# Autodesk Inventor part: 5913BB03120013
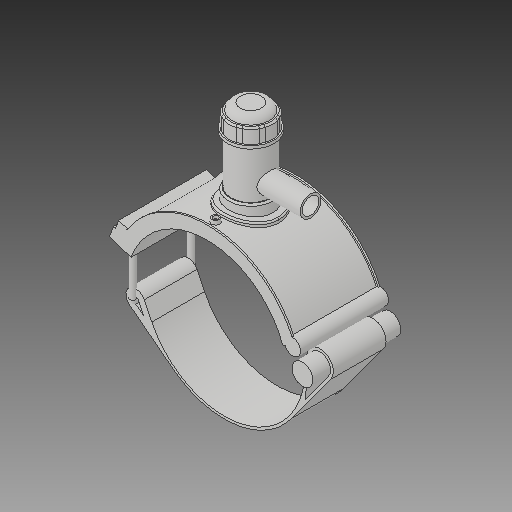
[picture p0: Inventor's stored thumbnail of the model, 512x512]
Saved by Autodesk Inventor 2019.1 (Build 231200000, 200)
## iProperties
Created: 2017-07
Part Number: 5913BB03120013
Material: Generic
Description: PLASSON HIGH VOLUME TAPPING TEE 12''IPS x 1 1/4''IPS
Document SubType Name: Modeling
Designer: KIM
Mass: 1712.7 g
Surface Area: 2671.49 cm^2
Volume: 1712.7 cm^3
Density: 1 g/cm^3
Appearance: Default
Author: KIM
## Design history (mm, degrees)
derived "5913B.ipt"
feature "Solid1::5913B.ipt"
feature "Solid2::5913B.ipt"
feature "Solid4::5913B.ipt"
feature "Solid5::5913B.ipt"
tag "TaggingFeature1"
body "Solid1"
body "Solid2"
other parameters: "d0" = 323.4, "d2" = 487.045, "d3" = 80.85, "d4" = 176.022, "d5" = 0, "d6" = 0.1, "d8" = 0, "d40" = 191.71152, "d41" = 113.19, "d43" = 0, "d45" = 0, "d47" = 289.9512, "d78" = 191.7, "d79" = 15, "d80" = 70.4088, "d82" = 5 deg, "d84" = 4, "d85" = 14, "d86" = 0, "d87" = 3, "d88" = 0, "d96" = 376.04952, "d97" = 3.52044, "d98" = 0, "d102" = 3.234, "d120" = 140 deg, "d121" = 24.228, "d122" = 20 deg, "d123" = 921.69, "d124" = 221.2056, "d126" = 0, "d153" = 176.022, "d154" = 0, "d159" = 9.0552, "d162" = 105.6132, "d163" = 0, "d164" = 161.7, "d169" = 4.0905, "d170" = 13.5828, "d172" = 0, "d173" = 1, "d175" = 161.7, "d176" = 20 deg, "d177" = 22.638, "d178" = 45.276, "d180" = 0, "d183" = 18.1104, "d184" = 18.1104, "d187" = 184.338, "d188" = 13.5828, "d189" = 22.638, "d190" = 0, "d191" = 276.507, "d193" = 11.6424, "d194" = 5.8212, "d195" = 90 deg, "d197" = 0, "d199" = 0, "d200" = 22.638, "d202" = 0, "d203" = 194.818, "d204" = 88.17501, "d205" = 64.97106, "d206" = 78.89343, "d207" = 146.1135, "d208" = 151.95804, "d209" = 181.18074, "d210" = 79.82159, "d211" = 92.8158, "d212" = 74.25264, "d213" = 48.492, "d216" = 0, "d217" = 32.34, "d218" = 16.17, "d219" = 3.234, "d222" = 323.4, "d224" = 0, "d230" = 3.234, "d257" = 236.63, "d258" = 119.888, "d259" = 33.68, "d260" = 42.1, "d263" = 194.818, "d265" = 0, "d267" = 13.00006, "d268" = 2.60001, "d269" = 2.60001, "d271" = 2.60001, "d273" = 0, "d274" = 23.56194, "d275" = 258.72, "d277" = 129.36, "d278" = 517.44, "d280" = 0, "d281" = 323.4, "d283" = 0, "d285" = 0, "d290" = 32.34, "d291" = 42.042, "d293" = 177.87, "d294" = 166.551, "d296" = 48.51, "d297" = 38.808, "d_" = 323.4, "B_" = 194.818, "L_" = 176.022, "d_t" = 6, "H_2" = 194.818, "H_1" = 74.93, "d_1" = 42.1, "H_" = 119.888, "d1" = 368.676, "d192" = 11.6424
